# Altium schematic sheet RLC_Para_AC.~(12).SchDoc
size A4
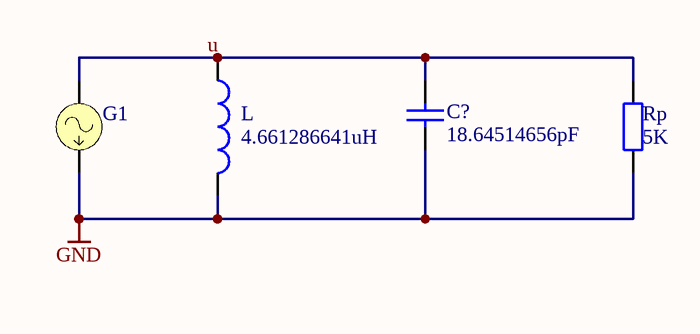
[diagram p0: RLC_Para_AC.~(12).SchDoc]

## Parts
C?  value 18.64514656pF  [RAD-0.3]  (hidden comment: Cap)
G1  ISIN  (value not drawn)
L  value 4.661286641uH  [0402-A]  (hidden comment: Inductor)
Rp  value 5K  [AXIAL-0.4]  (hidden comment: Res2)

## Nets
GND: C?.1 G1.2 L.2 Rp.2
u: C?.2 G1.1 L.1 Rp.1

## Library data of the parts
C? = Cap: Capacitor
G1 = ISIN: Sinusoidal Current Source
L = Inductor: Code_IEC: 1005
Rp = Res2: Resistor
